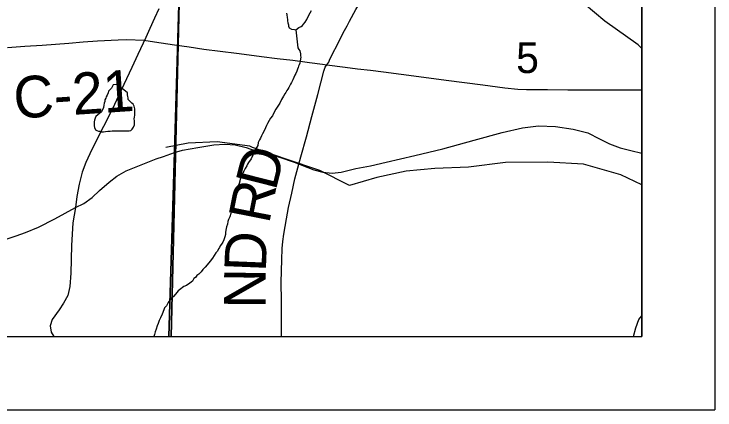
# Model space of a CAD drawing. Extents: x -6.1 to 38, y -7.7 to 22.
# Drawn here: x 8.043 to 9, y 14 to 14.54 of the extents above; entities that cross this region are included whole.
import ezdxf

# ---------------------------------------------------------------- set-up
doc = ezdxf.new("R2010")
doc.units = 0
for name, color, linetype in [('GM_X_Corporation', 7, 'Continuous'), ('GM_X_County_Road', 7, 'Continuous'), ('GM_X_County_Road_Text', 7, 'Continuous'), ('GM_X_Minor_Lake', 7, 'Continuous'), ('GM_X_Minor_River', 7, 'Continuous'), ('GM_X_Section_Text', 7, 'Continuous'), ('GM_X_Township_Road', 7, 'Continuous'), ('GM_X_Township_Road_Text', 7, 'Continuous'), ('SH_Data', 7, 'Continuous')]:
    doc.layers.add(name, color=color, linetype=linetype)

msp = doc.modelspace()

# ---------------------------------------------------------------- linework, layer by layer
at = {"layer": 'GM_X_Corporation'}
for points in [[(3.19219, 14.1), (8.25437, 14.1), (8.26188, 14.35188), (8.27757, 14.87811), (8.1023, 14.88375), (7.88923, 14.89059), (7.27984, 14.90301), (6.7864, 14.92029), (6.27951, 14.93803), (5.74746, 14.95956), (5.18977, 14.97327), (5.0967, 14.97556), (4.28061, 14.99995), (4.24786, 15.00093), (3.22473, 15.03847), (3.22164, 14.89402), (3.20818, 14.53184), (3.19363, 14.14313)], [(7.25364, 14.1), (8.25716, 14.1), (8.27613, 14.8776), (7.89065, 14.88943), (7.58452, 14.89838), (7.28457, 14.90716)], [(8.25437, 14.1), (8.9, 14.1), (8.9, 14.85918), (8.6137, 14.86789), (8.27757, 14.87811), (8.26188, 14.35188)], [(8.25716, 14.1), (8.9, 14.1), (8.9, 14.86439), (8.88117, 14.86479), (8.35974, 14.87583), (8.27613, 14.8776)], [(7.09053, 14.1), (8.9, 14.1), (8.9, 14.68725), (8.5875, 14.68029), (7.55487, 14.65733), (7.08348, 14.64684), (7.08792, 14.30249), (7.08793, 14.30152)]]:
    msp.add_lwpolyline(points, close=True, dxfattribs=at)
at = {"layer": 'GM_X_County_Road'}
for points in [[(8.24048, 14.54714), (8.23468, 14.53413), (8.22841, 14.52043), (8.22283, 14.50788), (8.21191, 14.48466), (8.20378, 14.46724), (8.18548, 14.42822), (8.17704, 14.41061), (8.16498, 14.38673), (8.14883, 14.35514), (8.14062, 14.33729), (8.1358, 14.32451), (8.1317, 14.30811), (8.12856, 14.29098), (8.12688, 14.27603)], [(8.03374, 14.49442), (8.05739, 14.49599), (8.08105, 14.49757), (8.09939, 14.49899), (8.11774, 14.50041), (8.13728, 14.50187), (8.15683, 14.50334), (8.18495, 14.50495), (8.19702, 14.50517), (8.21998, 14.50417), (8.23467, 14.50203), (8.26209, 14.49791), (8.2821, 14.49509), (8.3021, 14.49227), (8.32443, 14.48941), (8.34675, 14.48654), (8.3638, 14.48429), (8.38086, 14.48204), (8.40207, 14.47944), (8.42327, 14.47684), (8.44645, 14.47373), (8.46412, 14.47159), (8.46988, 14.47082), (8.49512, 14.46748), (8.51169, 14.46538), (8.52943, 14.46322), (8.54716, 14.46105), (8.57138, 14.45786), (8.60219, 14.45382), (8.63299, 14.44978), (8.65803, 14.4465), (8.68307, 14.44321), (8.71316, 14.43919), (8.73056, 14.43757), (8.74271, 14.43713), (8.7711, 14.437), (8.799, 14.43674), (8.83007, 14.43663), (8.9, 14.43657)], [(8.12688, 14.27603), (8.12326, 14.25529), (8.12109, 14.22418), (8.12013, 14.18656), (8.11916, 14.16823), (8.11602, 14.15616), (8.11048, 14.14555), (8.10421, 14.13639), (8.0948, 14.12336), (8.09215, 14.11468), (8.09335, 14.10624), (8.09695, 14.1)], [(8.88869, 14.1), (8.89202, 14.11209), (8.8962, 14.12347), (8.9, 14.12849)]]:
    msp.add_lwpolyline(points, dxfattribs=at)
at = {"layer": 'GM_X_Minor_Lake'}
for points in [[(8.41507, 14.54099), (8.41512, 14.53872), (8.41557, 14.5353), (8.41639, 14.53266), (8.41643, 14.53076), (8.41686, 14.52811), (8.41769, 14.52509), (8.41773, 14.52319), (8.41853, 14.52131), (8.42161, 14.51947), (8.42581, 14.51881), (8.42772, 14.51847), (8.43184, 14.5216), (8.43485, 14.52318), (8.43673, 14.52436), (8.43821, 14.52629), (8.44043, 14.52901), (8.44264, 14.53247), (8.44556, 14.53824), (8.44885, 14.54477)], [(8.17827, 14.44331), (8.1775, 14.44235), (8.17568, 14.43889), (8.17344, 14.43656), (8.17196, 14.43463), (8.17124, 14.43271), (8.16979, 14.42926), (8.1687, 14.42695), (8.16798, 14.42504), (8.16689, 14.42274), (8.16656, 14.42045), (8.16584, 14.41853), (8.16551, 14.41587), (8.16483, 14.41243), (8.16375, 14.40937), (8.16229, 14.40667), (8.15967, 14.40434), (8.15705, 14.40238), (8.15444, 14.40004), (8.15373, 14.39775), (8.15264, 14.39506), (8.15231, 14.39278), (8.152, 14.38973), (8.15204, 14.38745), (8.15247, 14.38518), (8.15406, 14.38217), (8.15598, 14.38108), (8.1579, 14.38036), (8.15981, 14.38002), (8.16211, 14.37931), (8.16515, 14.37937), (8.1678, 14.37981), (8.17084, 14.38026), (8.17388, 14.38032), (8.17691, 14.38077), (8.17958, 14.38083), (8.18262, 14.38051), (8.18529, 14.38057), (8.19746, 14.38045), (8.20012, 14.38089), (8.2024, 14.38094), (8.20426, 14.38288), (8.2061, 14.38558), (8.20717, 14.38903), (8.20711, 14.39169), (8.20706, 14.39434), (8.207, 14.397), (8.20733, 14.39929), (8.20766, 14.40196), (8.20761, 14.40424), (8.20755, 14.4069), (8.20789, 14.4088), (8.20785, 14.4107), (8.20701, 14.41449), (8.20543, 14.41711), (8.2035, 14.41859), (8.20039, 14.42156), (8.19883, 14.42343), (8.1984, 14.4257), (8.19798, 14.42759), (8.19755, 14.42986), (8.1975, 14.43252), (8.18378, 14.44375)], [(8.18378, 14.44375), (8.17827, 14.44331)]]:
    msp.add_lwpolyline(points, dxfattribs=at)
at = {"layer": 'GM_X_Minor_River'}
for points in [[(8.9, 14.49303), (8.895, 14.49773), (8.84962, 14.53023), (8.80725, 14.56615), (8.7679, 14.59981), (8.72854, 14.63914), (8.6956, 14.67849), (8.65738, 14.71139), (8.63166, 14.73029), (8.60778, 14.77193), (8.60815, 14.77496), (8.58765, 14.81737), (8.56752, 14.86622), (8.55985, 14.9132), (8.55407, 14.96018), (8.55093, 15.00754), (8.55159, 15.04506), (8.5628, 15.09094), (8.55325, 15.13336), (8.55919, 15.17544), (8.55643, 15.22053), (8.55449, 15.24251)], [(8.42772, 14.51847), (8.43053, 14.49383), (8.43172, 14.49157), (8.4329, 14.4897), (8.43375, 14.48554), (8.4338, 14.48288), (8.43422, 14.48098), (8.4339, 14.4787), (8.43358, 14.47565), (8.43287, 14.47297), (8.43216, 14.47068), (8.43144, 14.46876), (8.43072, 14.46685), (8.43001, 14.46455), (8.42893, 14.46187), (8.42747, 14.4588), (8.42638, 14.45649), (8.42347, 14.45035), (8.42165, 14.44651), (8.42017, 14.4442), (8.41945, 14.44228), (8.41799, 14.43959), (8.41651, 14.43766), (8.41541, 14.43573), (8.41394, 14.43304), (8.41246, 14.43111), (8.41063, 14.42803), (8.40806, 14.42341), (8.40589, 14.41842), (8.40293, 14.41418), (8.40035, 14.41032), (8.39816, 14.40609), (8.3956, 14.4011), (8.393, 14.398), (8.39118, 14.39454), (8.38897, 14.39069), (8.38751, 14.388), (8.38606, 14.38455), (8.38388, 14.37994), (8.38205, 14.37648), (8.38058, 14.37379), (8.37913, 14.37072), (8.37804, 14.36841), (8.37622, 14.36457), (8.37554, 14.36076), (8.37297, 14.35614), (8.37078, 14.35191), (8.36898, 14.34732), (8.36641, 14.3427), (8.36309, 14.33769), (8.36162, 14.33537), (8.36053, 14.33307), (8.35833, 14.32922), (8.3565, 14.32576), (8.35541, 14.32346), (8.35432, 14.32077), (8.35324, 14.31809), (8.35179, 14.31502), (8.35109, 14.31196), (8.35001, 14.3089), (8.34894, 14.30583), (8.34786, 14.30277), (8.34716, 14.3001), (8.3461, 14.29627), (8.34505, 14.29169), (8.34185, 14.28136), (8.34153, 14.27869), (8.34083, 14.27564), (8.33975, 14.27257), (8.33871, 14.26799), (8.33729, 14.2634), (8.33584, 14.25995), (8.33476, 14.25688), (8.33407, 14.25345), (8.33301, 14.24962), (8.3323, 14.24733), (8.33197, 14.24504), (8.33165, 14.242), (8.33133, 14.23933), (8.33064, 14.23589), (8.3292, 14.23206), (8.32775, 14.22899), (8.32591, 14.22591), (8.32443, 14.22397), (8.32334, 14.22167), (8.32186, 14.21974), (8.3204, 14.21667), (8.31855, 14.21435), (8.31597, 14.21049), (8.31376, 14.20702), (8.31081, 14.20278), (8.30635, 14.19774), (8.30375, 14.19464), (8.30077, 14.19154), (8.29818, 14.18844), (8.2952, 14.18534), (8.29258, 14.18338), (8.29035, 14.18067)], [(8.9, 14.30696), (8.8713, 14.32073), (8.82067, 14.33503), (8.77159, 14.33797), (8.71383, 14.33749), (8.66326, 14.33133), (8.61759, 14.32935), (8.57834, 14.32587), (8.53835, 14.31709), (8.501, 14.30603), (8.46018, 14.3268), (8.41295, 14.34263), (8.36837, 14.35809), (8.36497, 14.3596), (8.32003, 14.36558), (8.28078, 14.36399), (8.24984, 14.35788)], [(8.29035, 14.18067), (8.2881, 14.17948), (8.28666, 14.17565), (8.28291, 14.17291), (8.27841, 14.16977), (8.27464, 14.16855), (8.26865, 14.16386), (8.26678, 14.1623), (8.26492, 14.16036), (8.26345, 14.15804), (8.26047, 14.15494), (8.25786, 14.1526), (8.25564, 14.14951), (8.25342, 14.14643), (8.25085, 14.14219), (8.24825, 14.13947), (8.24755, 14.13642), (8.24501, 14.13066), (8.24283, 14.12568), (8.241, 14.12222), (8.23957, 14.118), (8.23812, 14.11455), (8.23707, 14.11035), (8.23563, 14.10652), (8.23457, 14.10269), (8.23374, 14.1)]]:
    msp.add_lwpolyline(points, dxfattribs=at)
at = {"layer": 'GM_X_Township_Road'}
for points in [[(8.49771, 14.52391), (8.50106, 14.53009), (8.50967, 14.54596), (8.51869, 14.56198), (8.5277, 14.57799), (8.5433, 14.60486), (8.5528, 14.62124), (8.56231, 14.63762), (8.57127, 14.65237), (8.58023, 14.66711), (8.58786, 14.67974), (8.58973, 14.68308)], [(8.46988, 14.47082), (8.47251, 14.4743), (8.47369, 14.47701), (8.47706, 14.48458), (8.48475, 14.4994), (8.49244, 14.51421), (8.49771, 14.52391)], [(8.40812, 14.1), (8.40811, 14.10105), (8.40795, 14.12213), (8.40787, 14.14818), (8.40779, 14.17422), (8.40838, 14.2049), (8.40914, 14.22015), (8.40999, 14.22971), (8.41118, 14.23988), (8.41466, 14.26076), (8.41748, 14.27632), (8.42194, 14.29584), (8.42639, 14.31537), (8.43456, 14.34535), (8.44201, 14.3727), (8.44946, 14.40005), (8.4575, 14.43007), (8.46177, 14.44599), (8.46604, 14.46192), (8.46788, 14.46748), (8.46988, 14.47082)], [(8.24665, 14.34576), (8.26209, 14.35134), (8.27277, 14.35412), (8.29377, 14.35803), (8.31548, 14.36165), (8.33043, 14.36261), (8.34466, 14.36165), (8.35986, 14.35779), (8.37892, 14.35133), (8.40517, 14.34459), (8.42537, 14.3381), (8.45209, 14.32741), (8.46463, 14.32416), (8.4774, 14.32276), (8.48948, 14.32416), (8.50969, 14.32927), (8.52943, 14.33298), (8.55103, 14.3381), (8.59006, 14.34715), (8.62815, 14.35621), (8.67112, 14.36782), (8.70945, 14.37828), (8.73732, 14.38478), (8.75892, 14.38733), (8.78215, 14.38641), (8.8063, 14.38292), (8.82628, 14.37781), (8.84208, 14.36992), (8.85601, 14.36294), (8.87065, 14.35761), (8.88528, 14.35389), (8.9, 14.35028)], [(8.0333, 14.23334), (8.0456, 14.23744), (8.05862, 14.24203), (8.07623, 14.2495), (8.09842, 14.26083), (8.12688, 14.27603), (8.13821, 14.28158), (8.14931, 14.28978), (8.15968, 14.29918), (8.1727, 14.31052), (8.18331, 14.31896), (8.19609, 14.3262), (8.237, 14.34228), (8.24665, 14.34576)]]:
    msp.add_lwpolyline(points, dxfattribs=at)
at = {"layer": 'SH_Data'}
for p, q in [((9, 21), (9, 14)), ((8.9, 20.9), (8.9, 14.1)), ((2.1, 14.1), (8.9, 14.1)), ((2, 14), (9, 14))]:
    msp.add_line(p, q, dxfattribs=at)

# ---------------------------------------------------------------- texts
at = {"layer": 'GM_X_County_Road_Text'}
msp.add_text('C-21', height=0.056818, rotation=3.76908, dxfattribs=at).set_placement((8.04384, 14.39713))
at = {"layer": 'GM_X_Section_Text'}
msp.add_text('5', height=0.04186, rotation=0.00001, dxfattribs=at).set_placement((8.72843, 14.45946))
at = {"layer": 'GM_X_Township_Road_Text'}
for s, rotation, p in [('D', 75.77467, (8.39986, 14.29759)), ('R', 78.7934, (8.39097, 14.25259)), ('D', 87.70079, (8.38656, 14.18765)), ('N', 89.60656, (8.38623, 14.13815))]:
    msp.add_text(s, height=0.05682, rotation=rotation, dxfattribs=at).set_placement(p)

doc.saveas('drawing.dxf')
